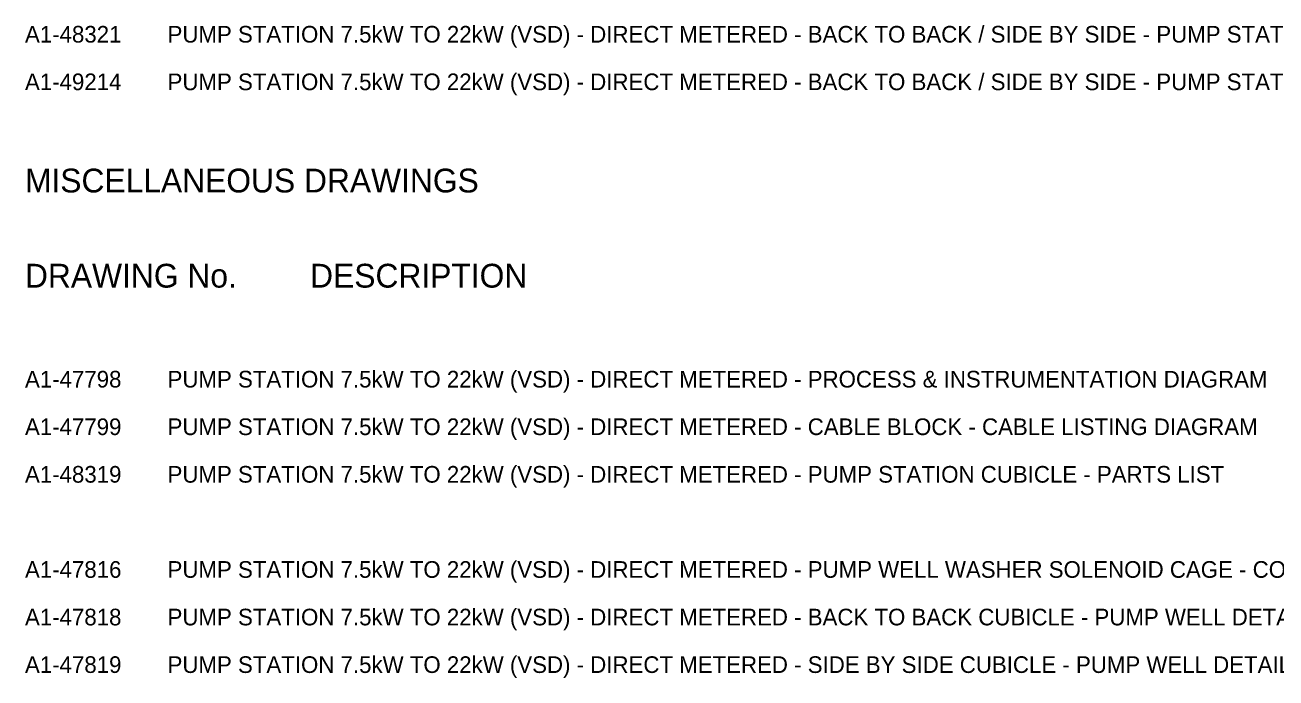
# Model space of a CAD drawing. Extents: x 0 to 841, y 0 to 594.
# Drawn here: x 440 to 703.2, y 160.4 to 297.7 of the extents above; entities that cross this region are included whole.
import ezdxf

# ---------------------------------------------------------------- set-up
doc = ezdxf.new("R2010")
doc.units = 0
doc.layers.add('Level 1', color=7, linetype='Continuous')

msp = doc.modelspace()

# ---------------------------------------------------------------- texts
at = {"layer": 'Level 1'}
for s, height, p in [('A1-48321', 3.5, (440, 294)), ('PUMP STATION 7.5kW TO 22kW (VSD) - DIRECT METERED - BACK TO BACK / SIDE BY SIDE - PUMP STATION CUBICLE - GEAR TRAY DRILLING DETAILS', 3.49998, (470, 294)), ('A1-49214', 3.5, (440, 284)), ('PUMP STATION 7.5kW TO 22kW (VSD) - DIRECT METERED - BACK TO BACK / SIDE BY SIDE - PUMP STATION CUBICLE - VSD DOOR DETAILS', 3.49998, (470, 284)), ('MISCELLANEOUS DRAWINGS', 5, (440, 262.5)), ('DRAWING No.', 5, (440, 242.5)), ('DESCRIPTION', 5, (500, 242.5)), ('A1-47798', 3.5, (440, 221.5)), ('PUMP STATION 7.5kW TO 22kW (VSD) - DIRECT METERED - PROCESS & INSTRUMENTATION DIAGRAM', 3.5, (470, 221.5)), ('A1-47799', 3.5, (440, 211.5)), ('PUMP STATION 7.5kW TO 22kW (VSD) - DIRECT METERED - CABLE BLOCK - CABLE LISTING DIAGRAM', 3.5, (470, 211.5)), ('A1-48319', 3.5, (440, 201.5)), ('PUMP STATION 7.5kW TO 22kW (VSD) - DIRECT METERED - PUMP STATION CUBICLE - PARTS LIST', 3.5, (470, 201.5)), ('A1-47816', 3.5, (440, 181.5)), ('PUMP STATION 7.5kW TO 22kW (VSD) - DIRECT METERED - PUMP WELL WASHER SOLENOID CAGE - CONSTRUCTION DIAGRAM', 3.49998, (470, 181.5)), ('A1-47818', 3.5, (440, 171.5)), ('PUMP STATION 7.5kW TO 22kW (VSD) - DIRECT METERED - BACK TO BACK CUBICLE - PUMP WELL DETAILS', 3.5, (470, 171.5)), ('A1-47819', 3.5, (440, 161.5)), ('PUMP STATION 7.5kW TO 22kW (VSD) - DIRECT METERED - SIDE BY SIDE CUBICLE - PUMP WELL DETAILS', 3.5, (470, 161.5))]:
    msp.add_text(s, height=height, dxfattribs=at).set_placement(p)

doc.saveas('drawing.dxf')
